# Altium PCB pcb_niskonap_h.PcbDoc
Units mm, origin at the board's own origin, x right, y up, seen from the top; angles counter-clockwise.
Board outline 22.1 x 25.27 mm, 2 copper layers (Top Layer, Bottom Layer); 9 components, 8 nets, 44 pads, 4 vias.
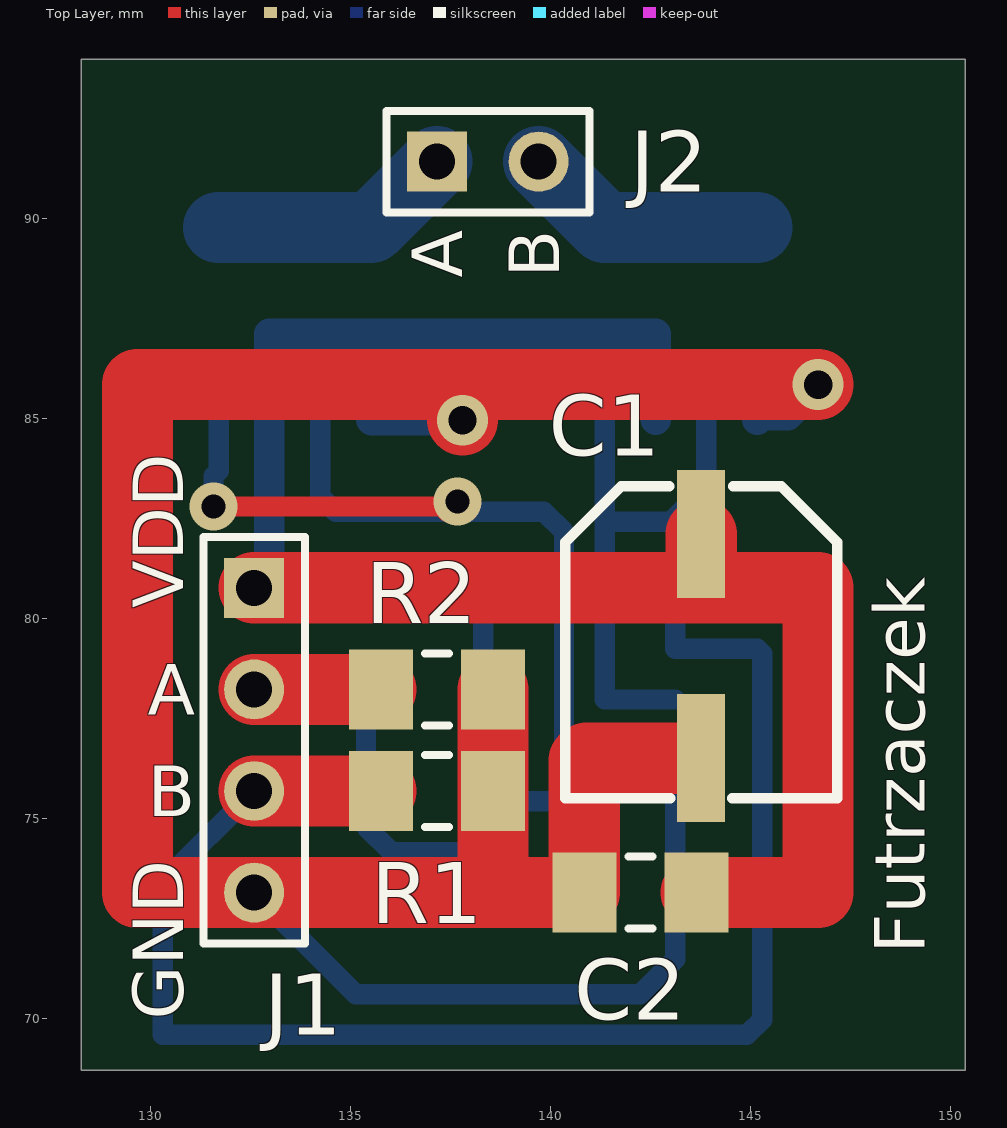
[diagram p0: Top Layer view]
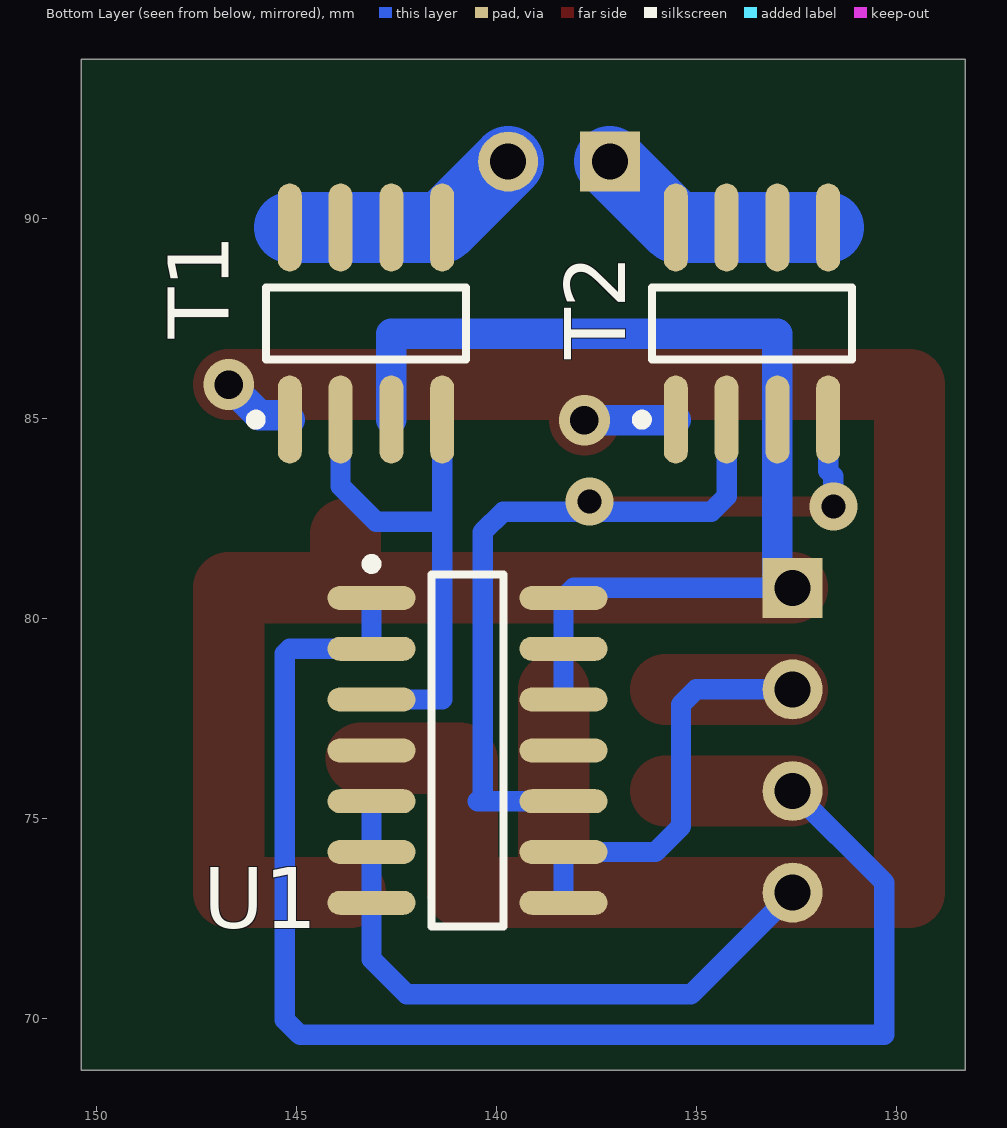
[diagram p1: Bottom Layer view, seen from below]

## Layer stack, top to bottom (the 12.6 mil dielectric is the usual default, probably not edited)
Top Layer: signal copper 0.0356
Dielectric: dielectric 0.32, FR-4, Dk 4.8
Bottom Layer: signal copper 0.0356

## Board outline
128.27,68.707 150.368,68.707 150.368,93.98 128.27,93.98

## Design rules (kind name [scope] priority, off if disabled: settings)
Clearance [All] p1: gap=0.254
PolygonConnect [All] p1: connectstyle=Relief reliefconductorwidth=0.254 reliefentries=4 polygonreliefangle="90 Angle"
RoutingVias [All] p1: holewidth=0.711 width=1.27 viastyle="Through Hole" minholewidth=0.711 minwidth=1.27 maxholewidth=0.711 maxwidth=1.27
SilkscreenOverComponentPads [All] p1: minsilkscreentomaskgap=0.254
SolderMaskExpansion [All] p1: expansion=0.102
Width [All] p1: maxlimit=2.54 minlimit=0.254 preferedwidth=1.27
27 further rules are at their usual default settings.

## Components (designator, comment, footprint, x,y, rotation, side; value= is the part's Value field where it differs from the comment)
C1 "100u/25V D" "D SMD elektrolit" 143.764,83.312 r180 top
C2 "100n 1206" MELF-1206 142.24,73.152 r0 top
J1 "Header 4" HDR1X4 132.588,80.772 r270 top
J2 "Header 2" HDR1X2 137.16,91.427 r0 top
R1 "100k" MELF-1206 137.16,75.692 r180 top
R2 "100k" MELF-1206 137.16,78.232 r180 top
T1 "IRF7307" SO-8_N 143.256,87.376 r90 bottom
T2 "IRF7307" SO-8_N 133.604,87.376 r90 bottom
U1 "CD4093" 751A-03_N 140.716,76.708 r180 bottom

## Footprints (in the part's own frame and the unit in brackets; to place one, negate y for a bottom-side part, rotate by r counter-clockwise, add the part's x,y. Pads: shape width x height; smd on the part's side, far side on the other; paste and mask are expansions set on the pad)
751A-03_N [mm] "SOIC, 14-Leads, Body 8.7x3.9mm, Pitch 1.27mm, IPC Medium Density"
  oval 2.2x0.6 smd: 1(-2.4,3.81) 2(-2.4,2.54) 3(-2.4,1.27) 4(-2.4,0) 5(-2.4,-1.27) 6(-2.4,-2.54) 7(-2.4,-3.81) 8(2.4,-3.81) 9(2.4,-2.54) 10(2.4,-1.27) 11(2.4,0) 12(2.4,1.27) 13(2.4,2.54) 14(2.4,3.81)
  silkscreen extent -2.53,-4.4 0.9,4.78, body extent -2,-4.38 2,4.38, height 1.75
"D SMD elektrolit" [mm]
  rect 1.2x3.2 smd: 1(0,1.2) 2(0,6.8)
  silkscreen extent -3.4,0 3.4,7.8
HDR1X2 [mm] "Connector; Header; 2 Position"
  rect 1.5x1.5 hole 0.9: 1(0,0)
  round 1.5 hole 0.9: 2(2.54,0)
  silkscreen extent -1.27,-1.27 3.81,1.27
HDR1X4 [mm] "Connector; Header; 4 Position"
  rect 1.5x1.5 hole 0.9: 1(0,0)
  round 1.5 hole 0.9: 2(2.54,0) 3(5.08,0) 4(7.62,0)
  silkscreen extent -1.27,-1.27 8.89,1.27
MELF-1206 [mm] "Metal Electrode Face (MELF) Resistor; Body 3.2 x 1.8 mm (LxDia)"
  rect 1.6x2 smd: 1(-1.4,0) 2(1.4,0)
  silkscreen extent -0.3,-0.9 0.3,0.9, body extent -2.3,-1.1 2.3,1.1, height 1.85
SO-8_N [mm] "SOIC, 8-Leads, Body 4.9x3.9mm, Pitch 1.27mm, IPC Medium Density"
  oval 2.2x0.6 smd: 1(-2.4,1.905) 2(-2.4,0.635) 3(-2.4,-0.635) 4(-2.4,-1.905) 5(2.4,-1.905) 6(2.4,-0.635) 7(2.4,0.635) 8(2.4,1.905)
  silkscreen extent -2.52,-2.5 0.9,2.88, body extent -1.95,-2.45 1.95,2.45, height 1.75

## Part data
C1: library part "kond biegunowy", "Polarized Capacitor"
C2: library part kondensator
J1: "Header, 4-Pin"
J2: "Header, 2-Pin"
R1 R2: library part rezystor
T1 T2: "HEXFET Power MOSFET"
U1: library part MC14093BD, "Quad 2-Input NAND Schmitt Trigger"

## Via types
v1: diameter 1.2, hole 0.6, Top Layer to Bottom Layer, 2 vias
v2: diameter 1.27, hole 0.711, Top Layer to Bottom Layer, 2 vias

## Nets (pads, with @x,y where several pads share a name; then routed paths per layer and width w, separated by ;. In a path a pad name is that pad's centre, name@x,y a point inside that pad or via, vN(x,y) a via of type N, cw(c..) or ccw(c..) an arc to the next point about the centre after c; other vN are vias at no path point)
GND: C1.2 C2.1 J1.4 R1.1 R2.1 T1.1 T2.1 U1.5 U1.6 U1.7 | length 72.9
  Top Layer w1.778: v2(137.795,84.963) 137.795,85.852 ; R2.1 R1.1 138.56,73.282 138.43,73.152 ; C1.2@143.383,76.512 140.901,76.512 140.84,76.451 C2.1 138.43,73.152 ; v2(146.685,85.852) 137.795,85.852 ; 137.795,85.852 129.667,85.852 129.667,73.152 J1.4 138.43,73.152
  Bottom Layer w0.508: J1.4 135.128,70.612 142.24,70.612 143.116,71.488 U1.7 U1.6 U1.5
  Bottom Layer w0.762: T2.1 135.522,84.963 v2(137.795,84.963) ; T1.1 145.275,85.09 145.923,85.09 v2(146.685,85.852)
NetJ1_2: J1.2 R2.2 U1.8 U1.9 | length 13.6
  Top Layer w1.778: J1.2 R2.2
  Bottom Layer w0.508: J1.2 135.001,78.232 135.382,77.851 135.382,74.803 136.017,74.168 U1.9 U1.8
NetJ1_3: J1.3 R1.2 U1.1 U1.2 | length 38
  Top Layer w1.778: J1.3 R1.2
  Bottom Layer w0.508: J1.3 130.302,73.406 130.302,69.596 144.907,69.596 145.288,69.977 145.288,75.438 145.288,79.121 145.161,79.248 U1.2 U1.1
NetJ2_1: J2.1 T2.5 T2.6 T2.7 T2.8 | length 6.1
  Bottom Layer w1.778: T2.5 T2.6 T2.7 T2.8 J2.1
NetJ2_2: J2.2 T1.5 T1.6 T1.7 T1.8 | length 6.1
  Bottom Layer w1.778: J2.2 T1.5 T1.6 T1.7 T1.8
NetT1_2: T1.2 T1.4 U1.3 | length 13.3
  Bottom Layer w0.508: T1.4 141.351,82.423 ; U1.3 141.351,77.978 141.351,82.423 ; T1.2 143.891,83.312 143.002,82.423 141.351,82.423
NetT2_2: T2.2 T2.4 U1.10 | length 25.4
  Top Layer w0.508: v1(131.572,82.804) 133.985,82.804 137.287,82.804 v1@137.414,82.677
  Bottom Layer w0.508: v1(131.572,82.804) 131.572,83.566 131.699,83.693 T2.4 ; T2.2 134.239,83.058 134.62,82.677 137.668,82.677 139.827,82.677 140.335,82.169 140.335,75.565 140.462,75.438 U1.10
  other v1: 137.668,82.931
VDD: C1.1 C2.2 J1.1 T1.3 T2.3 U1.12 U1.13 U1.14 | length 52.9
  Top Layer w1.778: J1.1 142.113,80.772 C1.1@143.383,80.772 ; C2.2 146.685,73.152 146.685,80.772 C1.1@143.383,80.772 ; C1.1 143.764,81.153 C1.1@143.383,80.772
  Bottom Layer w0.508: J1.1 138.062,80.772 U1.14 U1.13 U1.12
  Bottom Layer w0.762: J1.1 132.969,81.153 T2.3 132.969,87.122 142.621,87.122 T1.3
pads on no net: U1.4 U1.11

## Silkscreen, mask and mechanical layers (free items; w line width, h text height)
Top Overlay:
  text "A" at 137.795,88.519 h1.27 r90
  text "B" at 140.208,88.519 h1.27 r90
  text "VDD" at 130.81,80.264 h1.27 r90
  text "A" at 129.921,77.597 h1.27
  text "B" at 129.921,75.057 h1.27
  text "Futrzaczek" at 149.352,71.628 h1.27 r90
  text "GND" at 130.81,69.977 h1.27 r90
